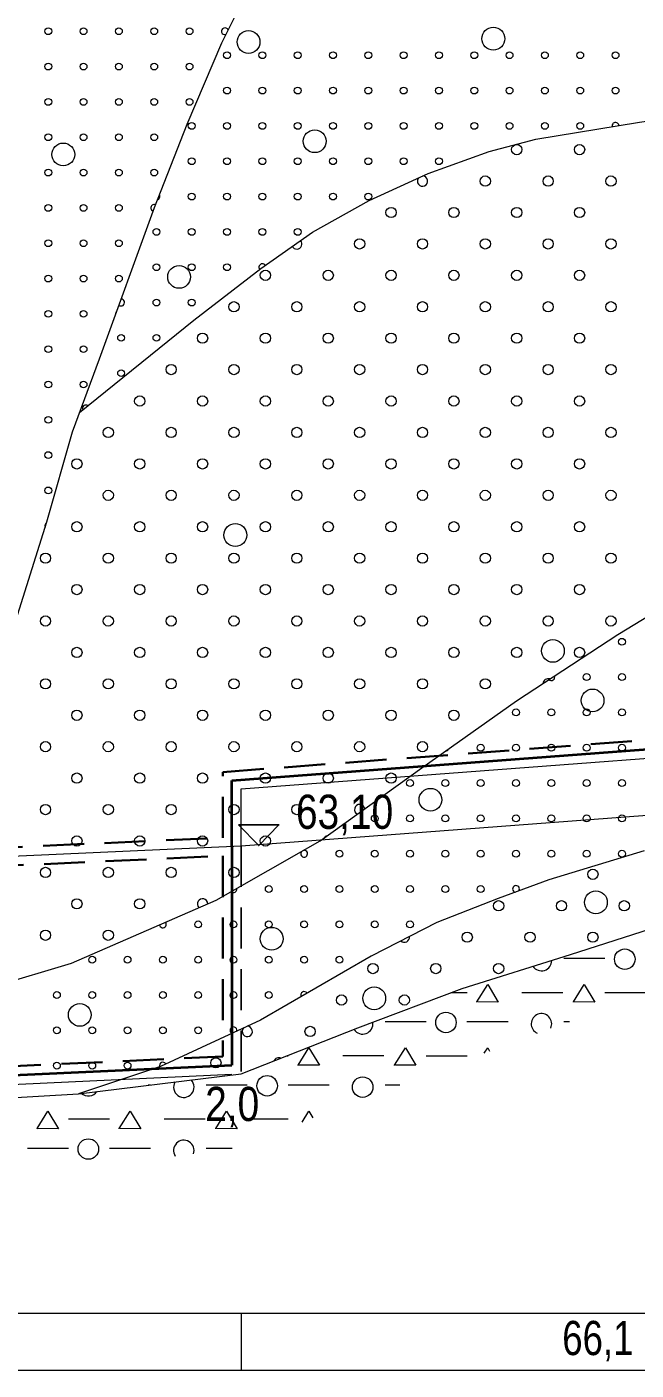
# Model space of a CAD drawing. Extents: x 640121 to 640955, y 6441885 to 6442246.
# Drawn here: x 640243.1 to 640296.5, y 6442063 to 6442180.9 of the extents above; entities that cross this region are included whole.
import ezdxf
from ezdxf.enums import TextEntityAlignment as Align

# ---------------------------------------------------------------- set-up
doc = ezdxf.new("R2010")
doc.units = 0
doc.header["$LTSCALE"] = 1.2
doc.linetypes.add('MEDIUM_DASHED', pattern=[4.5, 3, -1.5])
for name, color, linetype, lineweight in [('30', 7, 'Continuous', 13), ('31', 7, 'Continuous', 13), ('32', 7, 'Continuous', 13), ('34', 7, 'Continuous', 25), ('35', 7, 'Continuous', 35), ('42', 7, 'Continuous', 13), ('43', 7, 'Continuous', 13), ('46', 7, 'Continuous', 13), ('47', 7, 'Continuous', 13)]:
    doc.layers.add(name, color=color, linetype=linetype, lineweight=lineweight)

msp = doc.modelspace()

# ---------------------------------------------------------------- linework, layer by layer
at = {"layer": '30'}
for p, q in [((640132.09, 6442068), (640510.5, 6442068)), ((640261.87, 6442068), (640261.87, 6442063)), ((640132.09, 6442063), (640510.5, 6442063))]:
    msp.add_line(p, q, dxfattribs=at)
at = {"layer": '31'}
for points in [[(640222.36, 6442091.67), (640226.75, 6442095.51), (640231.91, 6442103.63), (640234.2, 6442108.11), (640235.67, 6442111.37), (640238.61, 6442118.45), (640241.77, 6442127.76), (640244.82, 6442137.43), (640247.07, 6442145.34), (640249.45, 6442151.75), (640254.26, 6442165.04), (640257.15, 6442172.33), (640260.17, 6442179.49), (640263.02, 6442185.17), (640266.2, 6442190.46), (640268.13, 6442192.87), (640269.38, 6442194.18), (640271.54, 6442195.96), (640274.5, 6442197.95), (640277.02, 6442199.46), (640278.7, 6442200.19), (640283.57, 6442201.67), (640288.47, 6442202.9)], [(640247.7, 6442147.03), (640257.72, 6442155.14), (640263.61, 6442159.68), (640268.14, 6442162.86), (640273.1, 6442165.63), (640278.29, 6442168.02), (640283.66, 6442169.95), (640287.74, 6442171.02), (640296.83, 6442172.52), (640307.85, 6442174.05), (640319.67, 6442175.43), (640328.02, 6442175.98), (640353.21, 6442179.27), (640361.87, 6442180.35), (640370.38, 6442181.71)], [(640227.02, 6442092.74), (640246.99, 6442098.72), (640259.67, 6442104.25), (640268.82, 6442109.45), (640277.74, 6442115.86), (640286.04, 6442121.74), (640294.93, 6442127.57), (640301.29, 6442131.41), (640306.79, 6442134.4), (640313.67, 6442137.73), (640318.09, 6442140.03), (640322.12, 6442142.41), (640327.78, 6442145.84), (640331.69, 6442148.58), (640336.02, 6442151.86), (640340.61, 6442155.98), (640344.72, 6442159.66), (640348.97, 6442163.76), (640353.58, 6442168.51), (640356.29, 6442171.26), (640360.44, 6442175.41), (640363.8, 6442178.7), (640365.59, 6442180.42)], [(640156.71, 6442084.57), (640169.39, 6442084.94), (640174.39, 6442085), (640185.27, 6442085.01), (640198.57, 6442085.15), (640211.29, 6442085.53), (640222.23, 6442086.04), (640236.05, 6442086.58), (640247.59, 6442087.26), (640261.87, 6442089), (640272.13, 6442093.03), (640281.27, 6442096.49), (640290.79, 6442099.48), (640306.37, 6442104.48), (640328.11, 6442110.01), (640342.33, 6442112.86), (640361.6, 6442115.89), (640378.77, 6442118.83), (640434.25, 6442118.61), (640476.5, 6442139.76), (640496.42, 6442148.93), (640502.36, 6442149.59), (640510.5, 6442150.13)], [(640297.25, 6442108.56), (640288.87, 6442106.02), (640284.44, 6442104.38), (640279.05, 6442102.27), (640273.28, 6442099.34), (640263.56, 6442093.7), (640254.81, 6442089.66), (640247.59, 6442087.26)]]:
    msp.add_lwpolyline(points, dxfattribs=at)
at = {"layer": '32', "linetype": 'MEDIUM_DASHED', "lineweight": 25}
msp.add_line((640261.87, 6442109), (640261.87, 6442089), dxfattribs=at)
at = {"layer": '34', "lineweight": 13}
msp.add_lwpolyline([(640159.63, 6442104.37), (640185.19, 6442105.55), (640261.87, 6442109), (640328.12, 6442114), (640360.69, 6442114.7)], dxfattribs=at)
at = {"layer": '34'}
msp.add_lwpolyline([(640261.63, 6442110.85), (640263.42, 6442109.04), (640265.19, 6442110.85)], close=True, dxfattribs=at)
at = {"layer": '35', "linetype": 'MEDIUM_DASHED'}
for p, q in [((640260.27, 6442109.72), (640260.27, 6442115.49)), ((640260.27, 6442108.12), (640260.27, 6442090.52)), ((640175.97, 6442086.67), (640260.27, 6442090.52))]:
    msp.add_line(p, q, dxfattribs=at)
at = {"layer": '35', "lineweight": 40}
for q in [(640261.07, 6442114.75), (640261.07, 6442089.76)]:
    msp.add_line((640261.07, 6442109), q, dxfattribs=at)
at = {"layer": '35', "lineweight": 13}
for p, q in [((640261.87, 6442109), (640261.87, 6442114.01)), ((640174.39, 6442085), (640261.07, 6442088.96))]:
    msp.add_line(p, q, dxfattribs=at)
at = {"layer": '35', "lineweight": 40}
for points in [[(640175.17, 6442195.66), (640175.17, 6442085.83), (640261.07, 6442089.76)], [(640261.07, 6442114.75), (640327.9, 6442119.79), (640434.15, 6442119.45)]]:
    msp.add_lwpolyline(points, dxfattribs=at)
at = {"layer": '35', "linetype": 'MEDIUM_DASHED'}
for points in [[(640260.27, 6442115.49), (640327.87, 6442120.59), (640433.96, 6442120.25)], [(640175.97, 6442105.93), (640185.15, 6442106.35), (640260.27, 6442109.72)], [(640175.97, 6442104.33), (640185.23, 6442104.75), (640260.27, 6442108.12)]]:
    msp.add_lwpolyline(points, dxfattribs=at)
at = {"layer": '35', "lineweight": 13}
msp.add_lwpolyline([(640261.87, 6442114.01), (640327.93, 6442118.99), (640434.96, 6442118.65)], dxfattribs=at)
at = {"layer": '42'}
for centre in [(640286.065, 6442170.107), (640291.58, 6442170.107), (640283.307, 6442167.349), (640288.822, 6442167.349), (640294.338, 6442167.349), (640275.034, 6442164.592), (640280.549, 6442164.592), (640286.065, 6442164.592), (640291.58, 6442164.592), (640272.276, 6442161.834), (640277.792, 6442161.834), (640283.307, 6442161.834), (640288.822, 6442161.834), (640294.338, 6442161.834), (640264.003, 6442159.076), (640269.518, 6442159.076), (640275.034, 6442159.076), (640280.549, 6442159.076), (640286.065, 6442159.076), (640291.58, 6442159.076), (640261.245, 6442156.318), (640266.761, 6442156.318), (640272.276, 6442156.318), (640277.792, 6442156.318), (640283.307, 6442156.318), (640288.822, 6442156.318), (640294.338, 6442156.318), (640258.488, 6442153.561), (640264.003, 6442153.561), (640269.518, 6442153.561), (640275.034, 6442153.561), (640280.549, 6442153.561), (640286.065, 6442153.561), (640291.58, 6442153.561), (640255.73, 6442150.803), (640261.245, 6442150.803), (640266.761, 6442150.803), (640272.276, 6442150.803), (640277.792, 6442150.803), (640283.307, 6442150.803), (640288.822, 6442150.803), (640294.338, 6442150.803), (640252.972, 6442148.045), (640258.488, 6442148.045), (640264.003, 6442148.045), (640269.518, 6442148.045), (640275.034, 6442148.045), (640280.549, 6442148.045), (640286.065, 6442148.045), (640291.58, 6442148.045), (640250.214, 6442145.288), (640255.73, 6442145.288), (640261.245, 6442145.288), (640266.761, 6442145.288), (640272.276, 6442145.288), (640277.792, 6442145.288), (640283.307, 6442145.288), (640288.822, 6442145.288), (640294.338, 6442145.288), (640247.457, 6442142.53), (640252.972, 6442142.53), (640258.488, 6442142.53), (640264.003, 6442142.53), (640269.518, 6442142.53), (640275.034, 6442142.53), (640280.549, 6442142.53), (640286.065, 6442142.53), (640291.58, 6442142.53), (640250.214, 6442139.772), (640255.73, 6442139.772), (640261.245, 6442139.772), (640266.761, 6442139.772), (640272.276, 6442139.772), (640277.792, 6442139.772), (640283.307, 6442139.772), (640288.822, 6442139.772), (640294.338, 6442139.772), (640247.457, 6442137.014), (640252.972, 6442137.014), (640258.488, 6442137.014), (640264.003, 6442137.014), (640269.518, 6442137.014), (640275.034, 6442137.014), (640280.549, 6442137.014), (640286.065, 6442137.014), (640291.58, 6442137.014), (640244.699, 6442134.257), (640250.214, 6442134.257), (640255.73, 6442134.257), (640261.245, 6442134.257), (640266.761, 6442134.257), (640272.276, 6442134.257), (640277.792, 6442134.257), (640283.307, 6442134.257), (640288.822, 6442134.257), (640294.338, 6442134.257), (640247.457, 6442131.499), (640252.972, 6442131.499), (640258.488, 6442131.499), (640264.003, 6442131.499), (640269.518, 6442131.499), (640275.034, 6442131.499), (640280.549, 6442131.499), (640286.065, 6442131.499), (640291.58, 6442131.499), (640244.699, 6442128.741), (640250.214, 6442128.741), (640255.73, 6442128.741), (640261.245, 6442128.741), (640266.761, 6442128.741), (640272.276, 6442128.741), (640277.792, 6442128.741), (640283.307, 6442128.741), (640288.822, 6442128.741), (640294.338, 6442128.741), (640247.457, 6442125.984), (640252.972, 6442125.984), (640258.488, 6442125.984), (640264.003, 6442125.984), (640269.518, 6442125.984), (640275.034, 6442125.984), (640280.549, 6442125.984), (640286.065, 6442125.984), (640291.58, 6442125.984), (640244.699, 6442123.226), (640250.214, 6442123.226), (640255.73, 6442123.226), (640261.245, 6442123.226), (640266.761, 6442123.226), (640272.276, 6442123.226), (640277.792, 6442123.226), (640283.307, 6442123.226), (640247.457, 6442120.468), (640252.972, 6442120.468), (640258.488, 6442120.468), (640264.003, 6442120.468), (640269.518, 6442120.468), (640275.034, 6442120.468), (640280.549, 6442120.468), (640244.699, 6442117.71), (640250.214, 6442117.71), (640255.73, 6442117.71), (640261.245, 6442117.71), (640266.761, 6442117.71), (640272.276, 6442117.71), (640277.792, 6442117.71), (640247.457, 6442114.953), (640252.972, 6442114.953), (640258.488, 6442114.953), (640264.003, 6442114.953), (640269.518, 6442114.953), (640275.034, 6442114.953), (640244.699, 6442112.195), (640250.214, 6442112.195), (640255.73, 6442112.195), (640261.245, 6442112.195), (640266.761, 6442112.195), (640247.457, 6442109.437), (640252.972, 6442109.437), (640258.488, 6442109.437), (640264.003, 6442109.437), (640244.699, 6442106.68), (640250.214, 6442106.68), (640255.73, 6442106.68), (640261.245, 6442106.68), (640292.75, 6442106.512), (640247.457, 6442103.922), (640252.972, 6442103.922), (640284.477, 6442103.754), (640289.992, 6442103.754), (640295.507, 6442103.754), (640244.699, 6442101.164), (640250.214, 6442101.164), (640281.719, 6442100.997), (640287.234, 6442100.997), (640292.75, 6442100.997), (640273.446, 6442098.239), (640278.961, 6442098.239), (640284.477, 6442098.239), (640270.688, 6442095.481), (640276.203, 6442095.481), (640267.93, 6442092.724), (640259.657, 6442089.966)]:
    msp.add_circle(centre, 0.45, dxfattribs=at)
for centre, start, end in [((640277.792, 6442167.349), 141.88682, 87.61329), ((640266.761, 6442161.834), 208.88183, 41.34219), ((640288.822, 6442123.226), 72.10013, 174.40861), ((640272.276, 6442112.195), 6.87727, 244.52552), ((640269.518, 6442109.437), 102.37085, 149.03194), ((640258.488, 6442103.922), 1.7127, 225.47694), ((640276.203, 6442100.997), 227.16506, 6.59606), ((640262.415, 6442092.724), 139.54305, 90.00723), ((640265.173, 6442089.966), 64.31649, 158.63534)]:
    msp.add_arc(centre, 0.45, start, end, dxfattribs=at)
at = {"layer": '43'}
for centre in [(640244.944, 6442180.496), (640248.044, 6442180.496), (640251.144, 6442180.496), (640254.244, 6442180.496), (640257.344, 6442180.496), (640260.638, 6442178.39), (640263.738, 6442178.39), (640266.838, 6442178.39), (640269.938, 6442178.39), (640273.038, 6442178.39), (640276.138, 6442178.39), (640279.238, 6442178.39), (640282.338, 6442178.39), (640285.438, 6442178.39), (640288.538, 6442178.39), (640291.638, 6442178.39), (640294.738, 6442178.39), (640244.944, 6442177.396), (640248.044, 6442177.396), (640251.144, 6442177.396), (640254.244, 6442177.396), (640257.344, 6442177.396), (640260.638, 6442175.29), (640263.738, 6442175.29), (640266.838, 6442175.29), (640269.938, 6442175.29), (640273.038, 6442175.29), (640276.138, 6442175.29), (640279.238, 6442175.29), (640282.338, 6442175.29), (640285.438, 6442175.29), (640288.538, 6442175.29), (640291.638, 6442175.29), (640294.738, 6442175.29), (640244.944, 6442174.296), (640248.044, 6442174.296), (640251.144, 6442174.296), (640254.244, 6442174.296), (640257.344, 6442174.296), (640257.538, 6442172.19), (640260.638, 6442172.19), (640263.738, 6442172.19), (640266.838, 6442172.19), (640269.938, 6442172.19), (640273.038, 6442172.19), (640276.138, 6442172.19), (640279.238, 6442172.19), (640282.338, 6442172.19), (640285.438, 6442172.19), (640288.538, 6442172.19), (640291.638, 6442172.19), (640244.944, 6442171.196), (640248.044, 6442171.196), (640251.144, 6442171.196), (640254.244, 6442171.196), (640257.538, 6442169.09), (640260.638, 6442169.09), (640263.738, 6442169.09), (640266.838, 6442169.09), (640269.938, 6442169.09), (640273.038, 6442169.09), (640276.138, 6442169.09), (640279.238, 6442169.09), (640244.944, 6442168.096), (640248.044, 6442168.096), (640251.144, 6442168.096), (640254.244, 6442168.096), (640244.944, 6442164.996), (640248.044, 6442164.996), (640251.144, 6442164.996), (640257.538, 6442165.99), (640260.638, 6442165.99), (640263.738, 6442165.99), (640266.838, 6442165.99), (640269.938, 6442165.99), (640273.038, 6442165.99), (640254.438, 6442162.89), (640257.538, 6442162.89), (640260.638, 6442162.89), (640263.738, 6442162.89), (640266.838, 6442162.89), (640244.944, 6442161.896), (640248.044, 6442161.896), (640251.144, 6442161.896), (640254.438, 6442159.79), (640257.538, 6442159.79), (640260.638, 6442159.79), (640244.944, 6442158.796), (640248.044, 6442158.796), (640251.144, 6442158.796), (640254.438, 6442156.69), (640257.538, 6442156.69), (640244.944, 6442155.696), (640248.044, 6442155.696), (640251.338, 6442153.59), (640254.438, 6442153.59), (640244.944, 6442152.596), (640248.044, 6442152.596), (640251.338, 6442150.49), (640244.944, 6442149.496), (640248.044, 6442149.496), (640244.944, 6442146.396), (640244.944, 6442143.296), (640244.944, 6442140.196), (640295.303, 6442126.92), (640292.203, 6442123.82), (640295.303, 6442123.82), (640286.003, 6442120.72), (640289.103, 6442120.72), (640292.203, 6442120.72), (640295.303, 6442120.72), (640282.903, 6442117.62), (640286.003, 6442117.62), (640289.103, 6442117.62), (640292.203, 6442117.62), (640295.303, 6442117.62), (640276.703, 6442114.52), (640279.803, 6442114.52), (640282.903, 6442114.52), (640286.003, 6442114.52), (640289.103, 6442114.52), (640292.203, 6442114.52), (640295.303, 6442114.52), (640273.603, 6442111.42), (640276.703, 6442111.42), (640279.803, 6442111.42), (640282.903, 6442111.42), (640286.003, 6442111.42), (640289.103, 6442111.42), (640292.203, 6442111.42), (640295.303, 6442111.42), (640270.503, 6442108.32), (640273.603, 6442108.32), (640276.703, 6442108.32), (640279.803, 6442108.32), (640282.903, 6442108.32), (640286.003, 6442108.32), (640289.103, 6442108.32), (640292.203, 6442108.32), (640295.303, 6442108.32), (640264.303, 6442105.22), (640267.403, 6442105.22), (640270.503, 6442105.22), (640273.603, 6442105.22), (640276.703, 6442105.22), (640279.803, 6442105.22), (640282.903, 6442105.22), (640258.103, 6442102.12), (640261.203, 6442102.12), (640264.303, 6442102.12), (640267.403, 6442102.12), (640270.503, 6442102.12), (640273.603, 6442102.12), (640276.703, 6442102.12), (640248.803, 6442099.02), (640251.903, 6442099.02), (640255.003, 6442099.02), (640258.103, 6442099.02), (640261.203, 6442099.02), (640264.303, 6442099.02), (640267.403, 6442099.02), (640270.503, 6442099.02), (640245.703, 6442095.92), (640248.803, 6442095.92), (640251.903, 6442095.92), (640255.003, 6442095.92), (640258.103, 6442095.92), (640261.203, 6442095.92), (640264.303, 6442095.92), (640245.703, 6442092.82), (640248.803, 6442092.82), (640251.903, 6442092.82), (640255.003, 6442092.82), (640258.103, 6442092.82), (640245.703, 6442089.72), (640248.803, 6442089.72), (640251.903, 6442089.72)]:
    msp.add_circle(centre, 0.3, dxfattribs=at)
for centre, start, end in [((640260.444, 6442180.496), 19.99557, 286.71304), ((640294.738, 6442172.19), 6.42773, 192.31288), ((640254.244, 6442164.996), 68.68037, 250.07024), ((640254.438, 6442165.99), 286.33034, 30.4196), ((640263.738, 6442159.79), 31.66192, 219.60263), ((640251.338, 6442156.69), 231.79412, 88.41284), ((640251.144, 6442155.696), 126.6207, 193.58626), ((640248.238, 6442147.39), 50.03169, 207.95014), ((640244.944, 6442137.096), 120.40351, 204.58506), ((640289.103, 6442123.82), 224.89646, 21.61228), ((640279.803, 6442117.62), 270.79187, 339.87865), ((640267.403, 6442108.32), 140.76537, 98.35222), ((640261.203, 6442105.22), 225.48952, 13.62807), ((640286.003, 6442105.22), 326.07834, 254.48678), ((640255.003, 6442102.12), 186.33629, 40.85336), ((640267.403, 6442095.92), 31.99036, 208.24204), ((640261.203, 6442092.82), 346.36348, 243.1868), ((640255.003, 6442089.72), 30.53758, 196.94444)]:
    msp.add_arc(centre, 0.3, start, end, dxfattribs=at)
at = {"layer": '46'}
for p, q in [((640293.8, 6442099.12), (640290.2, 6442099.12)), ((640281.71, 6442096.12), (640280.27, 6442096.12)), ((640290.1, 6442096.12), (640286.5, 6442096.12)), ((640297.4, 6442096.12), (640293.8, 6442096.12)), ((640278.11, 6442093.56), (640274.51, 6442093.56)), ((640285.3, 6442093.56), (640281.7, 6442093.56)), ((640290.7, 6442093.56), (640290.2, 6442093.56)), ((640266.01, 6442090.56), (640265.85, 6442090.56)), ((640274.41, 6442090.57), (640270.81, 6442090.57)), ((640281.71, 6442090.56), (640278.11, 6442090.56)), ((640253.91, 6442088), (640253.7, 6442088)), ((640262.41, 6442088.01), (640258.81, 6442088.01)), ((640269.61, 6442088), (640266.01, 6442088)), ((640275.8, 6442088.01), (640274.51, 6442088.01)), ((640250.31, 6442085.01), (640246.71, 6442085.01)), ((640258.71, 6442085.01), (640255.11, 6442085.01)), ((640266.01, 6442085.01), (640262.41, 6442085.01)), ((640246.71, 6442082.45), (640243.11, 6442082.45)), ((640253.91, 6442082.45), (640250.31, 6442082.45)), ((640261.09, 6442082.45), (640258.81, 6442082.45))]:
    msp.add_line(p, q, dxfattribs=at)
for points in [[(640282.57, 6442095.29), (640282.57, 6442095.31), (640283.52, 6442096.84), (640284.45, 6442095.3), (640282.65, 6442095.31)], [(640291.04, 6442095.29), (640291.04, 6442095.31), (640291.99, 6442096.84), (640292.92, 6442095.3), (640291.12, 6442095.31)], [(640266.87, 6442089.73), (640266.87, 6442089.76), (640267.82, 6442091.29), (640268.75, 6442089.75), (640266.95, 6442089.76)], [(640275.34, 6442089.73), (640275.35, 6442089.76), (640276.29, 6442091.29), (640277.22, 6442089.75), (640275.42, 6442089.76)], [(640283.22, 6442090.81), (640283.52, 6442091.29), (640283.69, 6442090.99)], [(640243.95, 6442084.18), (640243.96, 6442084.2), (640244.9, 6442085.73), (640245.83, 6442084.19), (640244.03, 6442084.2)], [(640251.17, 6442084.18), (640251.18, 6442084.2), (640252.13, 6442085.73), (640253.06, 6442084.19), (640251.26, 6442084.2)], [(640259.65, 6442084.18), (640259.65, 6442084.2), (640260.6, 6442085.73), (640261.53, 6442084.19), (640259.73, 6442084.2)], [(640267.22, 6442084.77), (640267.82, 6442085.73), (640268.18, 6442085.13)]]:
    msp.add_lwpolyline(points, dxfattribs=at)
for centre in [(640295.549, 6442099.064), (640279.853, 6442093.51), (640264.158, 6442087.955), (640272.54, 6442087.833), (640248.463, 6442082.401)]:
    msp.add_circle(centre, 0.9, dxfattribs=at)
for centre, start, end in [((640288.236, 6442098.942), 213.74203, 1.03192), ((640272.54, 6442093.387), 213.05017, 8.7573), ((640288.236, 6442093.387), 335.62206, 245.76884), ((640248.463, 6442087.955), 227.66297, 326.21538), ((640256.845, 6442087.833), 149.52708, 44.35127), ((640256.845, 6442082.279), 340.82551, 213.42453)]:
    msp.add_arc(centre, 0.9, start, end, dxfattribs=at)
at = {"layer": '47'}
for centre in [(640262.524, 6442179.553), (640284.013, 6442179.843), (640268.332, 6442170.841), (640246.262, 6442169.68), (640256.426, 6442158.935), (640261.363, 6442136.285), (640289.24, 6442126.122), (640292.724, 6442121.766), (640278.495, 6442113.054), (640293.015, 6442104.052), (640264.557, 6442100.858), (640273.559, 6442095.631), (640247.714, 6442094.179)]:
    msp.add_circle(centre, 1, dxfattribs=at)

# ---------------------------------------------------------------- texts
at = {"layer": '30', "width": 0.8}
msp.add_text('66,1', height=3, dxfattribs=at).set_placement((640293.185, 6442064.32), align=Align.CENTER)
at = {"layer": '32', "width": 0.85}
msp.add_text('2,0', height=3, dxfattribs=at).set_placement((640261.09, 6442084.86), align=Align.CENTER)
at = {"layer": '34', "width": 0.85}
msp.add_text('63,10', height=3, dxfattribs=at).set_placement((640270.955, 6442110.5), align=Align.CENTER)

doc.saveas('drawing.dxf')
